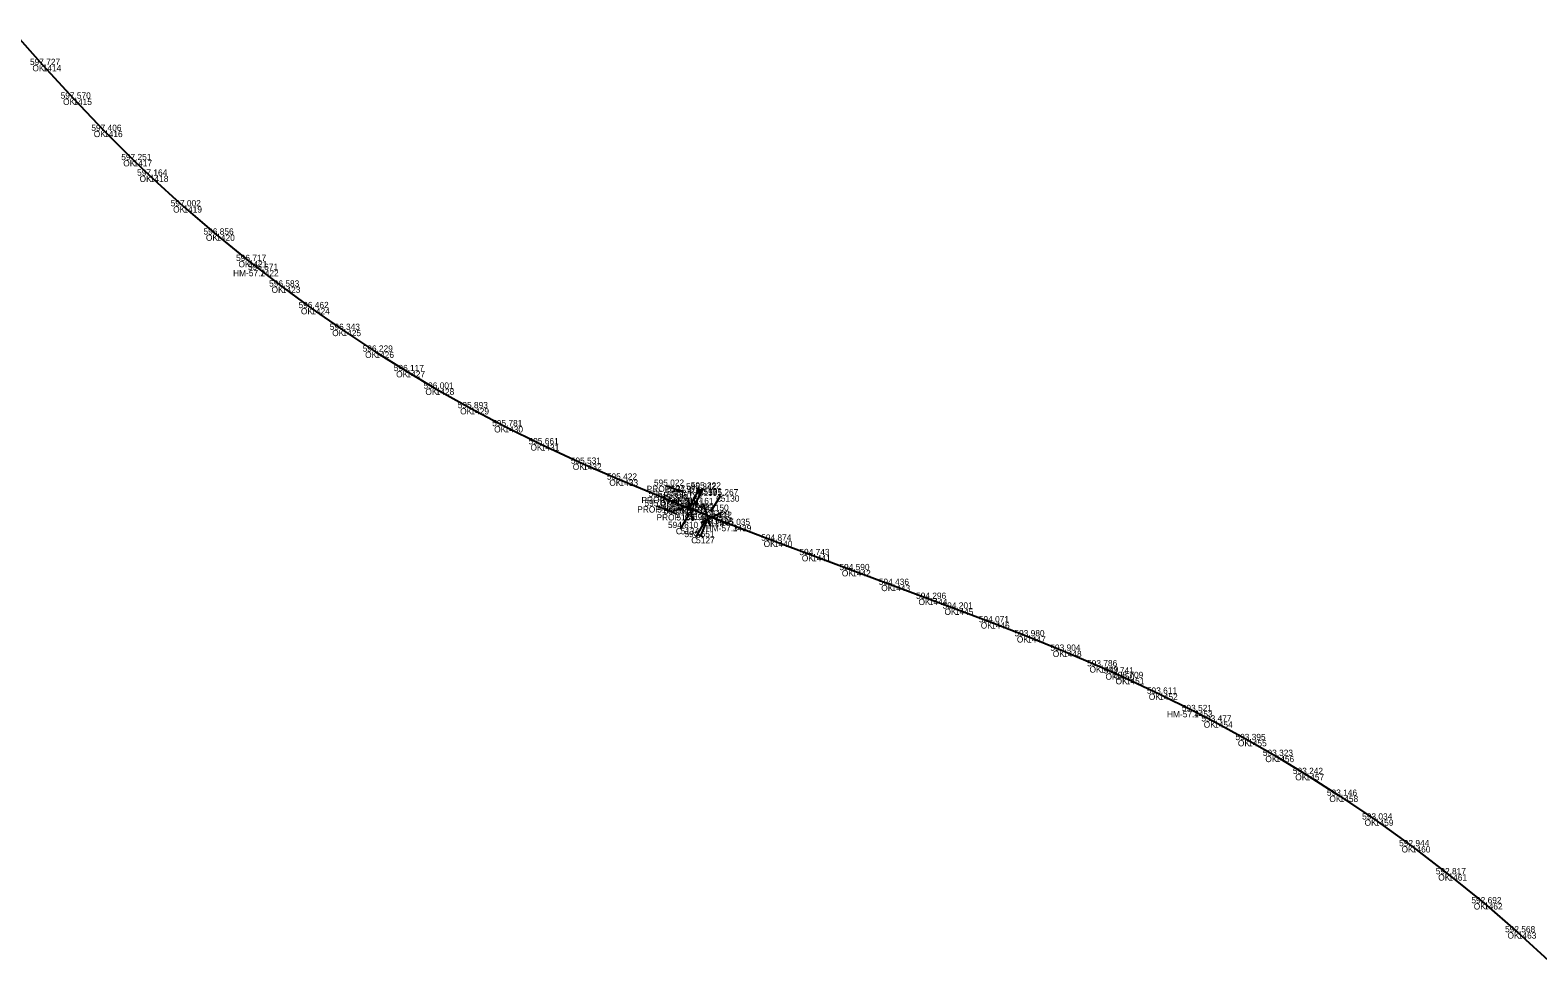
# Model space of a CAD drawing. Extents: x -631472 to -620808, y -1122356 to -1115125.
# Drawn here: x -624490.6 to -624200.5, y -1119109.1 to -1118929.4 of the extents above; entities that cross this region are included whole.
import ezdxf

# ---------------------------------------------------------------- set-up
doc = ezdxf.new("R2010")
doc.units = 0
for name, color, linetype in [('Vrstva 1', 7, 'Continuous'), ('Vrstva 18', 7, 'Continuous'), ('Vrstva 4', 7, 'Continuous'), ('Vrstva 51', 7, 'Continuous'), ('Vrstva 60', 7, 'Continuous'), ('Vrstva 61', 7, 'Continuous'), ('Vrstva 62', 7, 'Continuous')]:
    doc.layers.add(name, color=color, linetype=linetype)

msp = doc.modelspace()

# ---------------------------------------------------------------- linework, layer by layer
at = {"layer": 'Vrstva 1'}
msp.add_lwpolyline([(-624494.17, -1118929.44), (-624488.23, -1118936.15), (-624482.33, -1118942.62), (-624476.42, -1118948.82), (-624470.75, -1118954.45), (-624467.61, -1118957.44), (-624461.15, -1118963.34), (-624454.83, -1118968.77), (-624448.57, -1118973.86), (-624446.39, -1118975.58), (-624442.21, -1118978.78), (-624436.55, -1118982.92), (-624430.54, -1118987.11), (-624424.2, -1118991.3), (-624418.22, -1118995.04), (-624412.6, -1118998.42), (-624405.92, -1119002.17), (-624399.37, -1119005.64), (-624392.39, -1119009.12), (-624384.25, -1119012.86), (-624377.22, -1119015.92), (-624369.18, -1119019.23), (-624367.49, -1119019.91), (-624365.43, -1119020.74), (-624364.58, -1119021.08), (-624358.95, -1119023.3), (-624355.44, -1119024.65), (-624347.52, -1119027.67), (-624340.17, -1119030.44), (-624332.46, -1119033.33), (-624324.88, -1119036.17), (-624317.72, -1119038.85), (-624312.71, -1119040.73), (-624305.73, -1119043.37), (-624298.79, -1119046.06), (-624291.88, -1119048.84), (-624284.81, -1119051.84), (-624281.73, -1119053.21), (-624279.79, -1119054.09), (-624273.39, -1119057.1), (-624266.67, -1119060.45), (-624262.82, -1119062.45), (-624256.26, -1119066.03), (-624250.98, -1119069.07), (-624245.21, -1119072.56), (-624238.66, -1119076.74), (-624231.88, -1119081.31), (-624224.76, -1119086.45), (-624217.71, -1119091.86), (-624210.87, -1119097.43), (-624204.38, -1119103.02), (-624197.78, -1119109.07)], dxfattribs=at)
at = {"layer": 'Vrstva 18'}
for p, q in [((-624368.16, -1119017.1), (-624364.95, -1119018.31)), ((-624366.29, -1119022.56), (-624369.98, -1119021.04))]:
    msp.add_line(p, q, dxfattribs=at)
at = {"layer": 'Vrstva 4'}
for p, q in [((-624361.54, -1119018.08), (-624362.41, -1119017.59)), ((-624362.26, -1119020.37), (-624366.59, -1119021.94)), ((-624363.11, -1119023.91), (-624364, -1119019.39)), ((-624361.97, -1119017.83), (-624363.7, -1119020.88)), ((-624361.11, -1119020.54), (-624359.75, -1119024.94)), ((-624364.58, -1119021.08), (-624358.95, -1119023.3)), ((-624361.6, -1119026.7), (-624360.21, -1119023.49)), ((-624361.58, -1119024.14), (-624357.44, -1119022.13)), ((-624362.06, -1119026.5), (-624361.14, -1119026.9))]:
    msp.add_line(p, q, dxfattribs=at)
at = {"layer": 'Vrstva 51'}
for p, q in [((-624362.69, -1119020.62), (-624361.07, -1119017.64)), ((-624359.58, -1119021.91), (-624357.73, -1119018.95)), ((-624365.46, -1119025.23), (-624363.75, -1119022.44)), ((-624362.49, -1119026.98), (-624360.66, -1119023.71))]:
    msp.add_line(p, q, dxfattribs=at)
at = {"layer": 'Vrstva 60'}
for p, q in [((-624488.23, -1118936.15), (-624488.23, -1118936.15)), ((-624482.33, -1118942.62), (-624482.33, -1118942.62)), ((-624476.42, -1118948.82), (-624476.42, -1118948.82)), ((-624470.75, -1118954.45), (-624470.75, -1118954.45)), ((-624467.61, -1118957.44), (-624467.61, -1118957.44)), ((-624461.15, -1118963.34), (-624461.15, -1118963.34)), ((-624454.83, -1118968.77), (-624454.83, -1118968.77)), ((-624448.57, -1118973.86), (-624448.57, -1118973.86)), ((-624446.39, -1118975.58), (-624446.39, -1118975.58)), ((-624442.21, -1118978.78), (-624442.21, -1118978.78)), ((-624436.55, -1118982.92), (-624436.55, -1118982.92)), ((-624430.54, -1118987.11), (-624430.54, -1118987.11)), ((-624424.2, -1118991.3), (-624424.2, -1118991.3)), ((-624418.22, -1118995.04), (-624418.22, -1118995.04)), ((-624412.6, -1118998.42), (-624412.6, -1118998.42)), ((-624405.92, -1119002.17), (-624405.92, -1119002.17)), ((-624399.37, -1119005.64), (-624399.37, -1119005.64)), ((-624392.39, -1119009.12), (-624392.39, -1119009.12)), ((-624384.25, -1119012.86), (-624384.25, -1119012.86)), ((-624377.22, -1119015.92), (-624377.22, -1119015.92)), ((-624369.18, -1119019.23), (-624369.18, -1119019.23)), ((-624367.49, -1119019.91), (-624367.49, -1119019.91)), ((-624365.43, -1119020.74), (-624365.43, -1119020.74)), ((-624364.58, -1119021.08), (-624364.58, -1119021.08)), ((-624358.95, -1119023.3), (-624358.95, -1119023.3)), ((-624355.44, -1119024.65), (-624355.44, -1119024.65)), ((-624347.52, -1119027.67), (-624347.52, -1119027.67)), ((-624340.17, -1119030.44), (-624340.17, -1119030.44)), ((-624332.46, -1119033.33), (-624332.46, -1119033.33)), ((-624324.88, -1119036.17), (-624324.88, -1119036.17)), ((-624317.72, -1119038.85), (-624317.72, -1119038.85)), ((-624312.71, -1119040.73), (-624312.71, -1119040.73)), ((-624305.73, -1119043.37), (-624305.73, -1119043.37)), ((-624298.79, -1119046.06), (-624298.79, -1119046.06)), ((-624291.88, -1119048.84), (-624291.88, -1119048.84)), ((-624284.81, -1119051.84), (-624284.81, -1119051.84)), ((-624281.73, -1119053.21), (-624281.73, -1119053.21)), ((-624279.79, -1119054.09), (-624279.79, -1119054.09)), ((-624273.39, -1119057.1), (-624273.39, -1119057.1)), ((-624266.67, -1119060.45), (-624266.67, -1119060.45)), ((-624262.82, -1119062.45), (-624262.82, -1119062.45)), ((-624256.26, -1119066.03), (-624256.26, -1119066.03)), ((-624250.98, -1119069.07), (-624250.98, -1119069.07)), ((-624245.21, -1119072.56), (-624245.21, -1119072.56)), ((-624238.66, -1119076.74), (-624238.66, -1119076.74)), ((-624231.88, -1119081.31), (-624231.88, -1119081.31)), ((-624224.76, -1119086.45), (-624224.76, -1119086.45)), ((-624217.71, -1119091.86), (-624217.71, -1119091.86)), ((-624210.87, -1119097.43), (-624210.87, -1119097.43)), ((-624204.38, -1119103.02), (-624204.38, -1119103.02))]:
    msp.add_line(p, q, dxfattribs=at)

# ---------------------------------------------------------------- texts
for s, p in [('1414', (-624488.23, -1118937.35)), ('1415', (-624482.33, -1118943.82)), ('1416', (-624476.42, -1118950.02)), ('1417', (-624470.75, -1118955.65)), ('1418', (-624467.61, -1118958.64)), ('1419', (-624461.15, -1118964.54)), ('1420', (-624454.83, -1118969.97)), ('1421', (-624448.57, -1118975.06)), ('1422', (-624446.39, -1118976.78)), ('1423', (-624442.21, -1118979.98)), ('1424', (-624436.55, -1118984.12)), ('1425', (-624430.54, -1118988.31)), ('1426', (-624424.2, -1118992.5)), ('1427', (-624418.22, -1118996.24)), ('1428', (-624412.6, -1118999.61)), ('1429', (-624405.92, -1119003.37)), ('1430', (-624399.37, -1119006.84)), ('1431', (-624392.39, -1119010.32)), ('1432', (-624384.25, -1119014.06)), ('1433', (-624377.22, -1119017.12)), ('5137', (-624368.16, -1119018.3)), ('5131', (-624361.07, -1119018.84)), ('1434', (-624369.18, -1119020.43)), ('1435', (-624367.49, -1119021.11)), ('5138', (-624364.95, -1119019.51)), ('5132', (-624362.69, -1119021.82)), ('5139', (-624361.97, -1119019.03)), ('5130', (-624357.73, -1119020.15)), ('5136', (-624369.98, -1119022.25)), ('5135', (-624366.29, -1119023.77)), ('1436', (-624365.43, -1119021.94)), ('1437', (-624364.58, -1119022.28)), ('5133', (-624363.75, -1119023.64)), ('5129', (-624359.58, -1119023.1)), ('1438', (-624358.95, -1119024.5)), ('5134', (-624365.46, -1119026.43)), ('5128', (-624360.66, -1119024.91)), ('1439', (-624355.44, -1119025.85)), ('5127', (-624362.49, -1119028.18)), ('1440', (-624347.52, -1119028.87)), ('1441', (-624340.17, -1119031.64)), ('1442', (-624332.46, -1119034.53)), ('1443', (-624324.88, -1119037.37)), ('1444', (-624317.72, -1119040.05)), ('1445', (-624312.71, -1119041.93)), ('1446', (-624305.73, -1119044.57)), ('1447', (-624298.79, -1119047.26)), ('1448', (-624291.88, -1119050.04)), ('1449', (-624284.81, -1119053.04)), ('1450', (-624281.73, -1119054.41)), ('1451', (-624279.79, -1119055.29)), ('1452', (-624273.39, -1119058.3)), ('1453', (-624266.67, -1119061.65)), ('1454', (-624262.82, -1119063.65)), ('1455', (-624256.26, -1119067.23)), ('1456', (-624250.98, -1119070.27)), ('1457', (-624245.21, -1119073.77)), ('1458', (-624238.66, -1119077.94)), ('1459', (-624231.88, -1119082.51)), ('1460', (-624224.76, -1119087.65)), ('1461', (-624217.71, -1119093.06)), ('1462', (-624210.87, -1119098.62)), ('1463', (-624204.38, -1119104.22))]:
    msp.add_text(s, height=1.2, dxfattribs=at).set_placement(p)
at = {"layer": 'Vrstva 61'}
for s, p in [('597.727', (-624490.68, -1118936.15)), ('597.570', (-624484.78, -1118942.62)), ('597.406', (-624478.87, -1118948.82)), ('597.251', (-624473.11, -1118954.45)), ('597.164', (-624470.06, -1118957.44)), ('597.002', (-624463.6, -1118963.34)), ('596.856', (-624457.29, -1118968.77)), ('596.717', (-624451.02, -1118973.86)), ('596.671', (-624448.74, -1118975.58)), ('596.583', (-624444.66, -1118978.78)), ('596.462', (-624439, -1118982.92)), ('596.343', (-624432.99, -1118987.11)), ('596.229', (-624426.66, -1118991.3)), ('596.117', (-624420.67, -1118995.04)), ('596.001', (-624414.96, -1118998.42)), ('595.893', (-624408.37, -1119002.17)), ('595.781', (-624401.73, -1119005.64)), ('595.661', (-624394.74, -1119009.12)), ('595.531', (-624386.61, -1119012.86)), ('595.422', (-624379.66, -1119015.92)), ('595.022', (-624370.61, -1119017.1)), ('594.974', (-624367.4, -1119018.31)), ('595.342', (-624364.42, -1119017.83)), ('595.222', (-624363.52, -1119017.64)), ('595.267', (-624360.18, -1119018.95)), ('595.078', (-624372.44, -1119021.04)), ('595.275', (-624371.64, -1119019.23)), ('595.236', (-624369.94, -1119019.91)), ('595.210', (-624367.88, -1119020.74)), ('595.201', (-624366.94, -1119021.08)), ('595.161', (-624364.94, -1119020.62)), ('595.150', (-624362.03, -1119021.91)), ('595.014', (-624368.74, -1119022.56)), ('595.132', (-624366.2, -1119022.44)), ('595.095', (-624363.12, -1119023.71)), ('595.112', (-624361.4, -1119023.3)), ('595.035', (-624357.9, -1119024.65)), ('594.810', (-624367.91, -1119025.23)), ('594.651', (-624364.75, -1119026.98)), ('594.874', (-624349.97, -1119027.67)), ('594.743', (-624342.62, -1119030.44)), ('594.590', (-624334.92, -1119033.33)), ('594.436', (-624327.33, -1119036.17)), ('594.296', (-624320.17, -1119038.85)), ('594.201', (-624315.07, -1119040.73)), ('594.071', (-624308.09, -1119043.37)), ('593.980', (-624301.24, -1119046.06)), ('593.904', (-624294.33, -1119048.84)), ('593.786', (-624287.26, -1119051.84)), ('593.741', (-624284.08, -1119053.21)), ('593.709', (-624282.25, -1119054.09)), ('593.611', (-624275.75, -1119057.1)), ('593.521', (-624269.03, -1119060.45)), ('593.477', (-624265.27, -1119062.45)), ('593.395', (-624258.71, -1119066.03)), ('593.323', (-624253.43, -1119069.07)), ('593.242', (-624247.66, -1119072.56)), ('593.146', (-624241.11, -1119076.74)), ('593.034', (-624234.33, -1119081.31)), ('592.944', (-624227.21, -1119086.45)), ('592.817', (-624220.16, -1119091.86)), ('592.692', (-624213.31, -1119097.43)), ('592.568', (-624206.83, -1119103.02))]:
    msp.add_text(s, height=1.2, dxfattribs=at).set_placement(p)
at = {"layer": 'Vrstva 62'}
for s, p in [('OK', (-624490.21, -1118937.35)), ('OK', (-624484.31, -1118943.82)), ('OK', (-624478.4, -1118950.02)), ('OK', (-624472.73, -1118955.65)), ('OK', (-624469.59, -1118958.64)), ('OK', (-624463.13, -1118964.54)), ('OK', (-624456.82, -1118969.97)), ('OK', (-624450.56, -1118975.06)), ('HM-57.2', (-624451.59, -1118976.78)), ('OK', (-624444.19, -1118979.98)), ('OK', (-624438.54, -1118984.12)), ('OK', (-624432.52, -1118988.31)), ('OK', (-624426.19, -1118992.5)), ('OK', (-624420.21, -1118996.24)), ('OK', (-624414.59, -1118999.61)), ('OK', (-624407.9, -1119003.37)), ('OK', (-624401.35, -1119006.84)), ('OK', (-624394.37, -1119010.32)), ('OK', (-624386.23, -1119014.06)), ('OK', (-624379.2, -1119017.12)), ('PROP', (-624372, -1119018.3)), ('C', (-624362, -1119018.84)), ('PROP', (-624373.01, -1119020.43)), ('OK', (-624369.48, -1119021.11)), ('PROP', (-624368.79, -1119019.51)), ('VKR', (-624364.78, -1119019.03)), ('C', (-624363.62, -1119021.82)), ('C', (-624358.66, -1119020.15)), ('PROP', (-624373.82, -1119022.25)), ('PROP', (-624370.12, -1119023.77)), ('PROP', (-624369.27, -1119021.94)), ('PRJ', (-624367.06, -1119022.28)), ('C', (-624364.69, -1119023.64)), ('PRJ', (-624361.44, -1119024.5)), ('C', (-624360.52, -1119023.1)), ('C', (-624366.39, -1119026.43)), ('C', (-624361.6, -1119024.91)), ('HM-57.3', (-624360.64, -1119025.85)), ('C', (-624363.43, -1119028.18)), ('OK', (-624349.5, -1119028.87)), ('OK', (-624342.15, -1119031.64)), ('OK', (-624334.45, -1119034.53)), ('OK', (-624326.87, -1119037.37)), ('OK', (-624319.7, -1119040.05)), ('OK', (-624314.7, -1119041.93)), ('OK', (-624307.72, -1119044.57)), ('OK', (-624300.77, -1119047.26)), ('OK', (-624293.86, -1119050.04)), ('OK', (-624286.79, -1119053.04)), ('OK', (-624283.71, -1119054.41)), ('OK', (-624281.78, -1119055.29)), ('OK', (-624275.38, -1119058.3)), ('HM-57.4', (-624271.88, -1119061.65)), ('OK', (-624264.81, -1119063.65)), ('OK', (-624258.24, -1119067.23)), ('OK', (-624252.96, -1119070.27)), ('OK', (-624247.2, -1119073.77)), ('OK', (-624240.64, -1119077.94)), ('OK', (-624233.86, -1119082.51)), ('OK', (-624226.75, -1119087.65)), ('OK', (-624219.69, -1119093.06)), ('OK', (-624212.85, -1119098.62)), ('OK', (-624206.36, -1119104.22))]:
    msp.add_text(s, height=1.2, dxfattribs=at).set_placement(p)

doc.saveas('drawing.dxf')
